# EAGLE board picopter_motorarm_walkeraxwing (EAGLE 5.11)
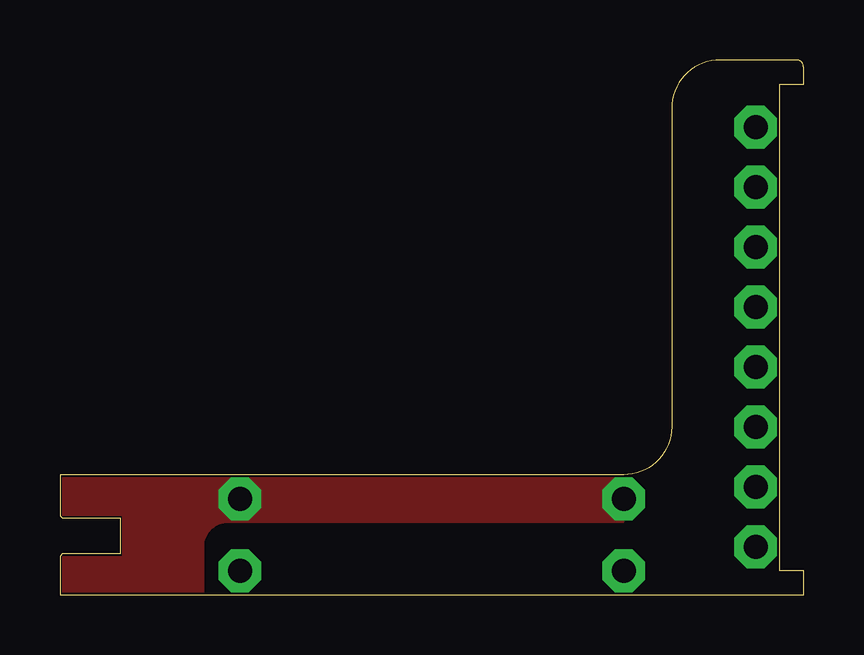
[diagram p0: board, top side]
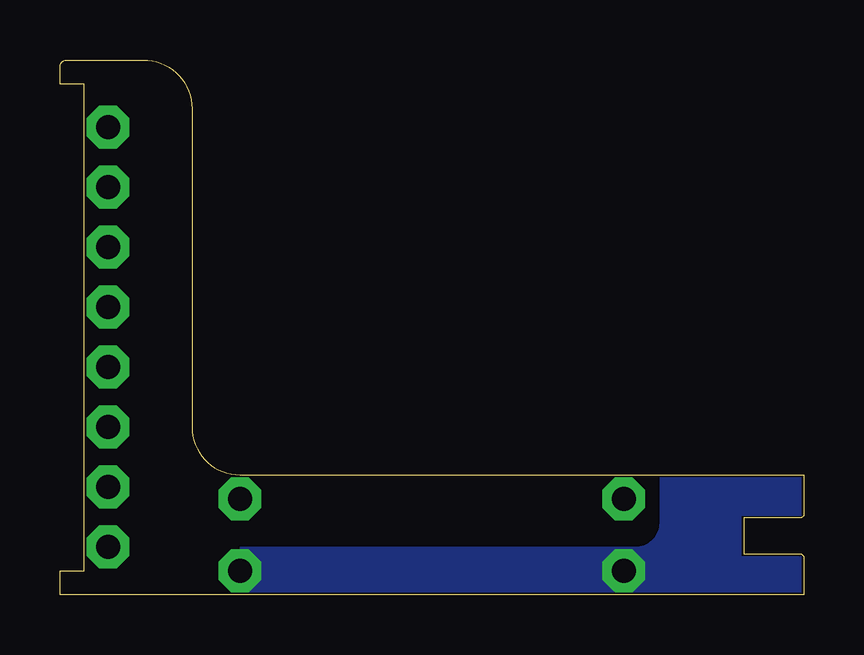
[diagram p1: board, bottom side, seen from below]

Size 31 x 22.3 mm. Coordinates in mm from the lower left corner, seen from the top.
Outline: 0,0 31,0 31,1 30,1 30,21.3 31,21.3 31,22 arc90 30.7,22.3 27.52,22.3 arc90 25.5,20.28 25.5,7 arc-90 23.5,5 0,5 0,3.3 0.1,3.2 2.5,3.2 2.5,1.7 0.1,1.7 0,1.6 0,0
Copper layers (1*16): Top 0.035mm / dielectric 1.5mm / Bottom 0.035mm
Design rules "default *": minimum track width 10mil, minimum drill 24mil, track to track 8mil, track to pad 8mil, pad to pad 8mil, via to via 8mil, smd to smd 8mil, copper to edge 0mil, drill to drill 8mil, minimum pad ring 10mil, minimum via ring 8mil, stop-mask expansion 4mil, vias tented up to drill 0mil, thermal gap 10mil

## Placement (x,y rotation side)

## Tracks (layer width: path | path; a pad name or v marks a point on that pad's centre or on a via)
S$1  (via drill 1 pad 1.78)
  other vias: 29,2
S$2  (via drill 1 pad 1.78)
  other vias: 29,4.5
S$3  (via drill 1 pad 1.78)
  other vias: 29,7
S$4  (via drill 1 pad 1.78)
  other vias: 29,9.5
S$5  (via drill 1 pad 1.78)
  other vias: 29,12
S$6  (via drill 1 pad 1.78)
  other vias: 29,14.5
S$7  (via drill 1 pad 1.78)
  other vias: 29,17
S$8  (via drill 1 pad 1.78)
  other vias: 29,19.5
S$9  (via drill 1 pad 1.78)
  other vias: 23.5,1 7.5,1
  pour Bottom: 0.1,0.1 23.5,0.1 23.5,2 7,2 arc-90 6,3 6,4.9 0.1,4.9 0.1,3.3 2.6,3.3 2.6,1.6 0.1,1.6
S$10  (via drill 1 pad 1.78)
  other vias: 23.5,4 7.5,4
  pour Top: 0.1,4.9 23.5,4.9 23.5,3 7,3 arc90 6,2 6,0.1 0.1,0.1 0.1,1.6 2.6,1.6 2.6,3.3 0.1,3.3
